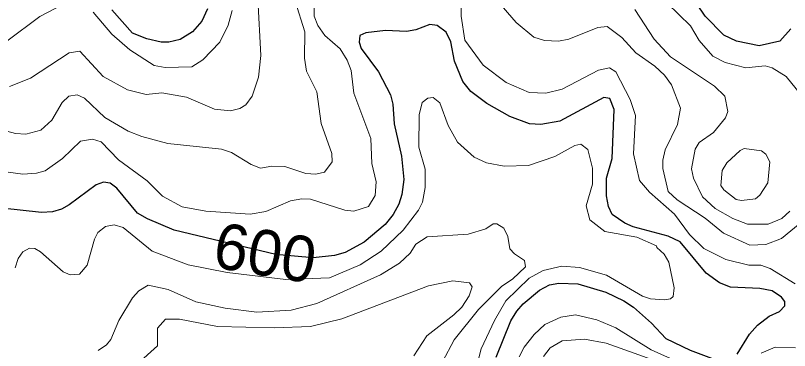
# Model space of a CAD drawing. Extents: x 673.3 to 698.5, y 6984.3 to 7012.3.
# Drawn here: x 680.463 to 681.82, y 6995.48 to 6996.068 of the extents above; entities that cross this region are included whole.
import ezdxf
from ezdxf.enums import TextEntityAlignment as Align

# ---------------------------------------------------------------- set-up
doc = ezdxf.new("R2010")
doc.units = 0
doc.header["$LTSCALE"] = 0.032
doc.layers.add('1', color=7, linetype='Continuous', lineweight=25)
doc.layers.add('2', color=7, linetype='Continuous', lineweight=13)
doc.layers.add('61', color=7, linetype='Continuous')

msp = doc.modelspace()

# ---------------------------------------------------------------- linework, layer by layer
at = {"layer": '1'}
for points in [[(681.822, 6996.0442), (681.8028, 6996.0226), (681.7668, 6996.0145), (681.7269, 6996.0226), (681.7049, 6996.0335), (681.6721, 6996.0666), (681.6304, 6996.1282)], [(680.7999, 6996.0795), (680.79, 6996.058), (680.7735, 6996.039), (680.7516, 6996.0259), (680.7321, 6996.0209), (680.7188, 6996.0209), (680.6936, 6996.0268), (680.668, 6996.0366), (680.632, 6996.0777)], [(681.7279, 6995.4738), (681.7499, 6995.5089), (681.7634, 6995.5246), (681.784, 6995.5403), (681.8019, 6995.5487), (681.8114, 6995.5588), (681.8115, 6995.5664), (681.8059, 6995.5737), (681.7893, 6995.5851), (681.7679, 6995.5892), (681.7162, 6995.5913), (681.6971, 6995.5989), (681.6736, 6995.6157), (681.6283, 6995.6706), (681.6072, 6995.6807), (681.5457, 6995.6974), (681.5309, 6995.7036), (681.5087, 6995.7188), (681.5027, 6995.733), (681.4989, 6995.7515), (681.499, 6995.7825), (681.5088, 6995.8171), (681.5127, 6995.9027), (681.5047, 6995.922), (681.4946, 6995.9238), (681.4172, 6995.8824), (681.3841, 6995.8768), (681.3639, 6995.8779), (681.3298, 6995.8904), (681.2893, 6995.9137), (681.2614, 6995.9343), (681.2471, 6995.9519), (681.2326, 6995.9877), (681.2262, 6996.0213), (681.2178, 6996.0383), (681.202, 6996.0502), (681.1895, 6996.0517), (681.1648, 6996.0424), (681.1484, 6996.0397), (681.1116, 6996.0412), (681.0773, 6996.0372), (681.0665, 6996.0327), (681.0657, 6996.0212), (681.0693, 6996.0098), (681.0992, 6995.9692), (681.1203, 6995.9285), (681.1243, 6995.9125), (681.1268, 6995.878), (681.1395, 6995.8212), (681.1439, 6995.7802), (681.1404, 6995.7538), (681.135, 6995.7369), (681.1253, 6995.719), (681.111, 6995.7014), (681.0741, 6995.67), (681.0409, 6995.6519), (681.0224, 6995.6469), (680.9847, 6995.643), (680.9196, 6995.6485), (680.7411, 6995.6915), (680.6946, 6995.7113), (680.6772, 6995.7213), (680.6408, 6995.7648), (680.6291, 6995.774), (680.6173, 6995.7756), (680.6045, 6995.7706), (680.5572, 6995.7355)], [(680.5572, 6995.7355), (680.5438, 6995.7283), (680.5279, 6995.7236), (680.5088, 6995.7221), (680.4393, 6995.7301)], [(681.3054, 6995.4686), (681.3316, 6995.5324), (681.3416, 6995.5491), (681.3529, 6995.5621), (681.3815, 6995.5862), (681.3993, 6995.5956), (681.4155, 6995.5982), (681.4487, 6995.5973), (681.4976, 6995.5826), (681.5295, 6995.5674), (681.5461, 6995.5566), (681.5776, 6995.5284), (681.6032, 6995.5013), (681.6458, 6995.4808), (681.6969, 6995.4616)]]:
    msp.add_lwpolyline(points, dxfattribs=at)
at = {"layer": '2'}
for points in [[(681.8298, 6995.5972), (681.7859, 6995.6241), (681.7693, 6995.6299), (681.7485, 6995.63), (681.7081, 6995.6396), (681.6695, 6995.6589), (681.6443, 6995.684), (681.618, 6995.7193), (681.5744, 6995.7581), (681.5568, 6995.7785), (681.5462, 6995.8252), (681.5501, 6995.8923), (681.5405, 6995.9204), (681.5152, 6995.9692), (681.5043, 6995.976), (681.4847, 6995.9718), (681.4213, 6995.9388), (681.3926, 6995.9316), (681.3634, 6995.9329), (681.3229, 6995.9501), (681.2827, 6995.9807), (681.2507, 6996.0246), (681.2441, 6996.0666), (681.2444, 6996.1159)], [(681.585, 6996.1099), (681.6463, 6996.0493), (681.6616, 6996.0236), (681.6856, 6995.9964), (681.7068, 6995.9853), (681.7429, 6995.9761), (681.7769, 6995.9794), (681.7894, 6995.9758), (681.8141, 6995.9606), (681.8388, 6995.93)], [(680.4528, 6995.9431), (680.4894, 6995.9577), (680.5575, 6996.0021), (680.5759, 6996.0053), (680.6169, 6995.9608), (680.6596, 6995.9373), (680.6924, 6995.9289), (680.7199, 6995.9321), (680.763, 6995.9246), (680.8119, 6995.9035), (680.8398, 6995.9004), (680.8566, 6995.9049), (680.8668, 6995.9109), (680.8781, 6995.9262), (680.8889, 6995.9597), (680.8931, 6995.9977), (680.8882, 6996.0977)], [(681.5502, 6996.0023), (681.5257, 6996.029), (681.4999, 6996.0486), (681.4841, 6996.0467), (681.4332, 6996.0261), (681.4148, 6996.0225), (681.3901, 6996.024), (681.3716, 6996.0296), (681.3409, 6996.0557), (681.3069, 6996.0951)], [(680.3183, 6996.0699), (680.3267, 6996.0534), (680.3477, 6996.0301), (680.4057, 6996.0119), (680.4334, 6996.0167), (680.4479, 6996.0227), (680.5058, 6996.0657), (680.5583, 6996.0933)], [(680.9533, 6996.0929), (680.9704, 6996.0393), (680.9696, 6995.9929), (680.9731, 6995.97), (680.9914, 6995.9339), (680.9988, 6995.8786), (681.0177, 6995.8259), (681.0184, 6995.811), (681.0048, 6995.7928), (680.9894, 6995.7896), (680.9722, 6995.7909), (680.9355, 6995.8027), (680.9125, 6995.8034), (680.8924, 6995.8003), (680.8765, 6995.8067), (680.8419, 6995.8274), (680.8243, 6995.8336), (680.7304, 6995.8432), (680.6848, 6995.8555), (680.6607, 6995.8649), (680.6199, 6995.8886), (680.5843, 6995.923), (680.5713, 6995.9288), (680.5569, 6995.9264), (680.5453, 6995.9149), (680.5269, 6995.8843), (680.5076, 6995.8664), (680.4816, 6995.8596), (680.4635, 6995.8609), (680.4393, 6995.8675)], [(680.9867, 6996.0816), (680.9868, 6996.0666), (680.9929, 6996.0501), (681.0056, 6996.0328), (681.0322, 6996.0094), (681.0447, 6995.9893), (681.0518, 6995.9712), (681.0562, 6995.9316), (681.086, 6995.8523), (681.0876, 6995.8084), (681.0956, 6995.776), (681.0934, 6995.752), (681.0818, 6995.7326), (681.0562, 6995.7245), (681.0406, 6995.7266), (680.9801, 6995.7455), (680.9651, 6995.7464), (680.945, 6995.7428), (680.9022, 6995.724), (680.8745, 6995.7196), (680.7969, 6995.7244), (680.7556, 6995.7323), (680.7206, 6995.7509), (680.6937, 6995.7778), (680.644, 6995.8146), (680.6133, 6995.8461), (680.5982, 6995.8506), (680.5771, 6995.8472), (680.5458, 6995.817), (680.5154, 6995.7954), (680.5002, 6995.7911), (680.4763, 6995.7896), (680.4501, 6995.7929)], [(680.5992, 6996.0736), (680.6322, 6996.0348), (680.6636, 6996.0076), (680.706, 6995.9801), (680.7256, 6995.9764), (680.7724, 6995.9777), (680.7917, 6995.9901), (680.8212, 6996.021), (680.8358, 6996.0508), (680.8429, 6996.0765)], [(681.5487, 6996.0784), (681.5825, 6996.0265), (681.6113, 6995.995), (681.6881, 6995.944), (681.7063, 6995.9265), (681.7114, 6995.8994), (681.7073, 6995.8881), (681.6867, 6995.8625), (681.6616, 6995.8451), (681.6544, 6995.8333), (681.648, 6995.7991), (681.6512, 6995.7826), (681.6673, 6995.7499), (681.6893, 6995.7296)], [(681.8448, 6995.7087), (681.8056, 6995.677), (681.778, 6995.6663), (681.7501, 6995.6653), (681.7039, 6995.6858), (681.6721, 6995.7123), (681.6229, 6995.7447), (681.6073, 6995.759), (681.5975, 6995.7995), (681.5975, 6995.8139), (681.6016, 6995.832), (681.6235, 6995.8768), (681.6285, 6995.9052), (681.6132, 6995.9461), (681.6009, 6995.9628), (681.5839, 6995.9789), (681.5502, 6996.0023)], [(680.4625, 6995.6254), (680.468, 6995.6418), (680.4759, 6995.6534), (680.4875, 6995.6599), (680.4969, 6995.6592), (680.5069, 6995.6535), (680.547, 6995.6182), (680.5591, 6995.6129), (680.5755, 6995.614), (680.5887, 6995.6297), (680.6018, 6995.6757), (680.6075, 6995.687), (680.6208, 6995.6978), (680.636, 6995.7007), (680.6521, 6995.6958), (680.7025, 6995.6544), (680.7657, 6995.6308), (680.8342, 6995.617), (680.9371, 6995.6048), (681.0135, 6995.608), (681.0671, 6995.6306), (681.1042, 6995.6547), (681.1424, 6995.6912), (681.1698, 6995.7266), (681.1765, 6995.7402), (681.1814, 6995.7662), (681.1813, 6995.7985), (681.1699, 6995.8371), (681.1708, 6995.8936), (681.176, 6995.9151), (681.1856, 6995.9229), (681.1955, 6995.9239), (681.2069, 6995.9148), (681.2217, 6995.8749), (681.2381, 6995.8459), (681.2668, 6995.8194), (681.2884, 6995.8091), (681.3195, 6995.8035), (681.3624, 6995.8045), (681.4085, 6995.8202), (681.4434, 6995.84), (681.4543, 6995.8422), (681.4664, 6995.8329), (681.4744, 6995.7998), (681.4744, 6995.7718), (681.4631, 6995.7337), (681.4695, 6995.7092), (681.4962, 6995.6891), (681.5521, 6995.6789), (681.5865, 6995.6641), (681.587, 6995.6609), (681.6, 6995.6495), (681.6082, 6995.6351), (681.6178, 6995.59), (681.6161, 6995.5748), (681.6112, 6995.5707), (681.6005, 6995.5689), (681.576, 6995.5711), (681.5622, 6995.5755), (681.4992, 6995.6127), (681.4517, 6995.6258), (681.4206, 6995.6283), (681.3879, 6995.6208), (681.3635, 6995.6069), (681.3223, 6995.5675), (681.3025, 6995.5329), (681.2793, 6995.4831), (681.263, 6995.4187)], [(681.6893, 6995.7296), (681.7202, 6995.7115), (681.7462, 6995.7016), (681.7825, 6995.7016), (681.8065, 6995.712), (681.8202, 6995.7249)], [(681.2117, 6995.4604), (681.232, 6995.4992), (681.2747, 6995.5524), (681.3154, 6995.593), (681.3344, 6995.6056), (681.3572, 6995.6271), (681.3553, 6995.6381), (681.3375, 6995.6496), (681.3296, 6995.6585), (681.3262, 6995.6801), (681.3188, 6995.695), (681.3069, 6995.7022), (681.3006, 6995.7024), (681.2877, 6995.6934), (681.2568, 6995.6843), (681.1846, 6995.6795), (681.1651, 6995.6665), (681.1549, 6995.6508), (681.136, 6995.6333), (681.1031, 6995.6128), (680.9911, 6995.5625), (680.9464, 6995.5509), (680.8859, 6995.5477)], [(680.8859, 6995.5477), (680.8308, 6995.5543), (680.7793, 6995.5656), (680.7307, 6995.5874), (680.696, 6995.5949), (680.6796, 6995.585), (680.6684, 6995.5728), (680.6446, 6995.5331), (680.6302, 6995.4994), (680.623, 6995.4902), (680.6083, 6995.4802)], [(680.6764, 6995.4562), (680.7122, 6995.4887), (680.7123, 6995.5194), (680.7259, 6995.5355), (680.7507, 6995.5355), (680.8175, 6995.5225), (680.9163, 6995.5201), (680.98, 6995.5223), (681.0353, 6995.5356), (681.1872, 6995.5935), (681.2296, 6995.6022), (681.2591, 6995.599), (681.2633, 6995.5917), (681.2586, 6995.5761), (681.2452, 6995.5565), (681.2315, 6995.5427), (681.1841, 6995.5058), (681.1616, 6995.4709)], [(681.3462, 6995.469), (681.3549, 6995.4861), (681.3725, 6995.5083), (681.3909, 6995.5258), (681.4191, 6995.5387), (681.4445, 6995.5427), (681.4823, 6995.5339), (681.5155, 6995.5198), (681.5774, 6995.4816), (681.6725, 6995.4391)], [(681.3883, 6995.4698), (681.4003, 6995.485), (681.4211, 6995.4973), (681.4605, 6995.5004), (681.4983, 6995.4933), (681.6275, 6995.4473)], [(681.77, 6995.4758), (681.7947, 6995.4864), (681.8305, 6995.485)]]:
    msp.add_lwpolyline(points, dxfattribs=at)
msp.add_lwpolyline([(681.7815, 6995.7744), (681.7855, 6995.8112), (681.7782, 6995.8245), (681.7706, 6995.8303), (681.74, 6995.8343), (681.7334, 6995.8311), (681.7098, 6995.8091), (681.7017, 6995.7957), (681.6996, 6995.7695), (681.7047, 6995.7622), (681.7261, 6995.7452), (681.7357, 6995.7432), (681.76, 6995.746), (681.7678, 6995.7524)], close=True, dxfattribs=at)

# ---------------------------------------------------------------- texts
at = {"layer": '61'}
msp.add_text('600', height=0.08, rotation=350.538, dxfattribs=at).set_placement((680.8943, 6995.6122), align=Align.CENTER)

doc.saveas('drawing.dxf')
